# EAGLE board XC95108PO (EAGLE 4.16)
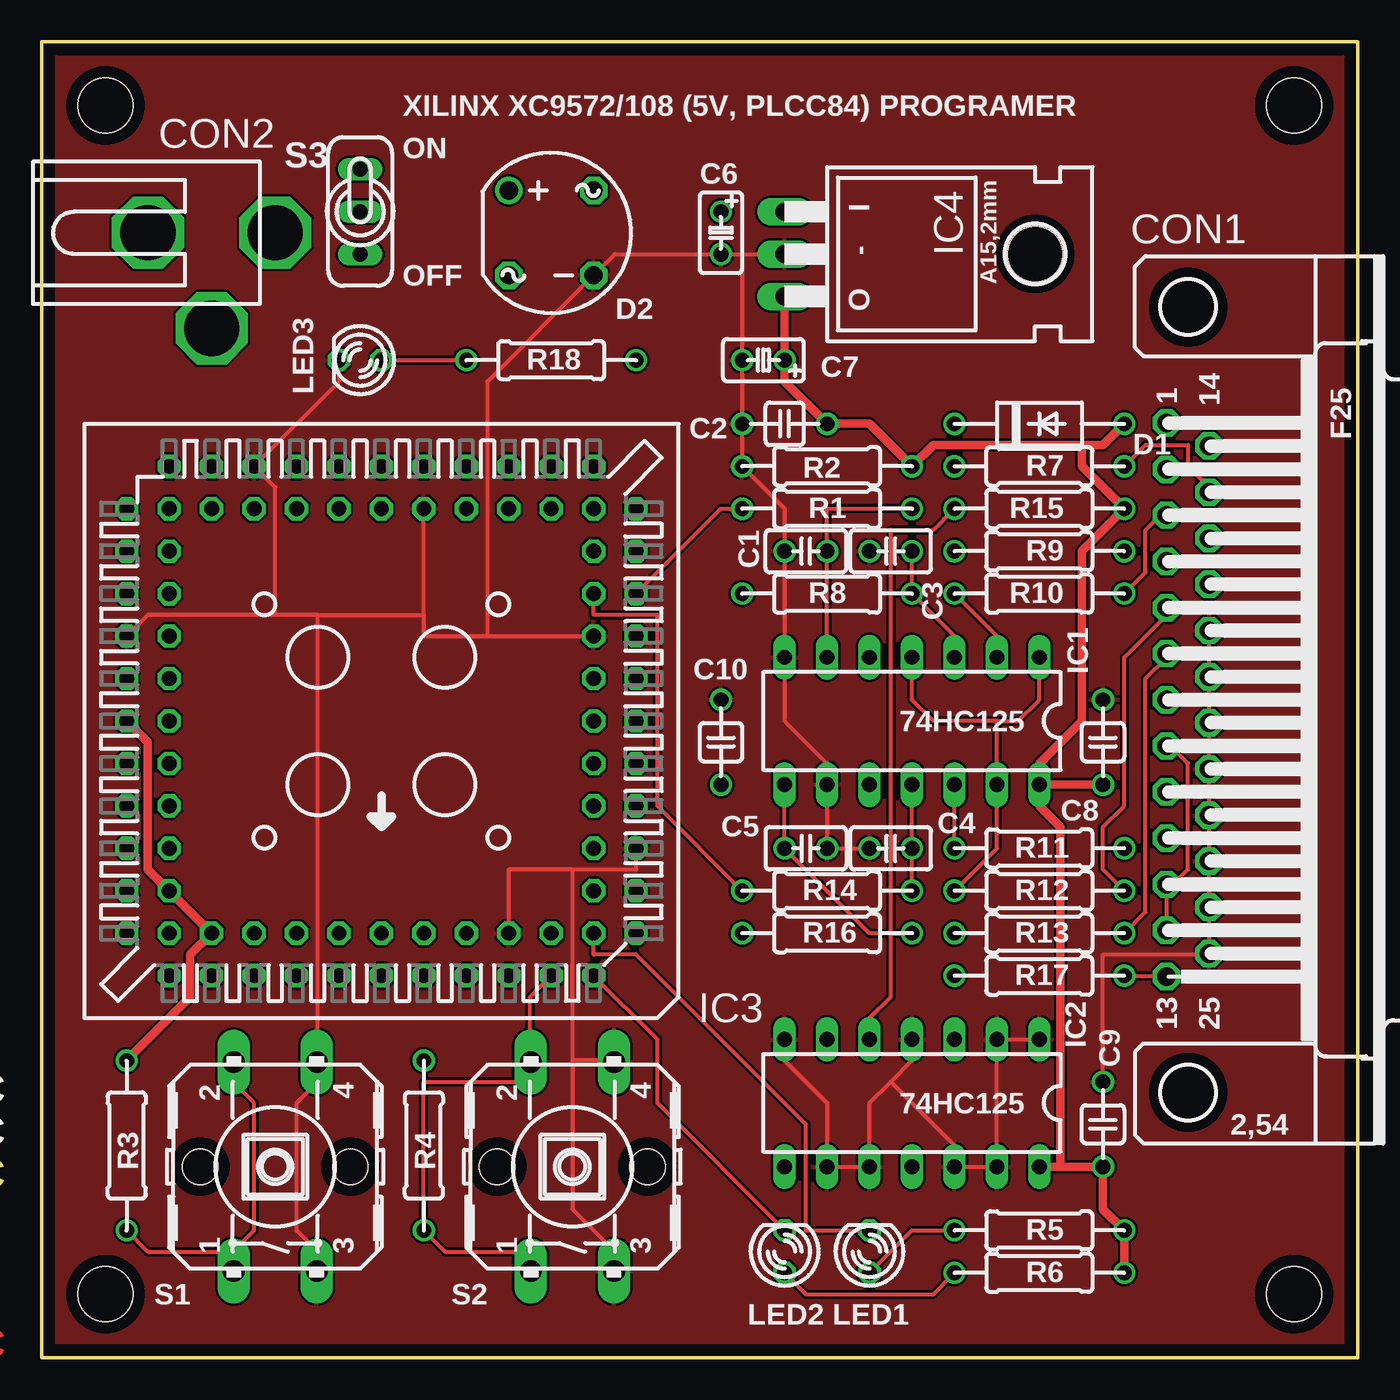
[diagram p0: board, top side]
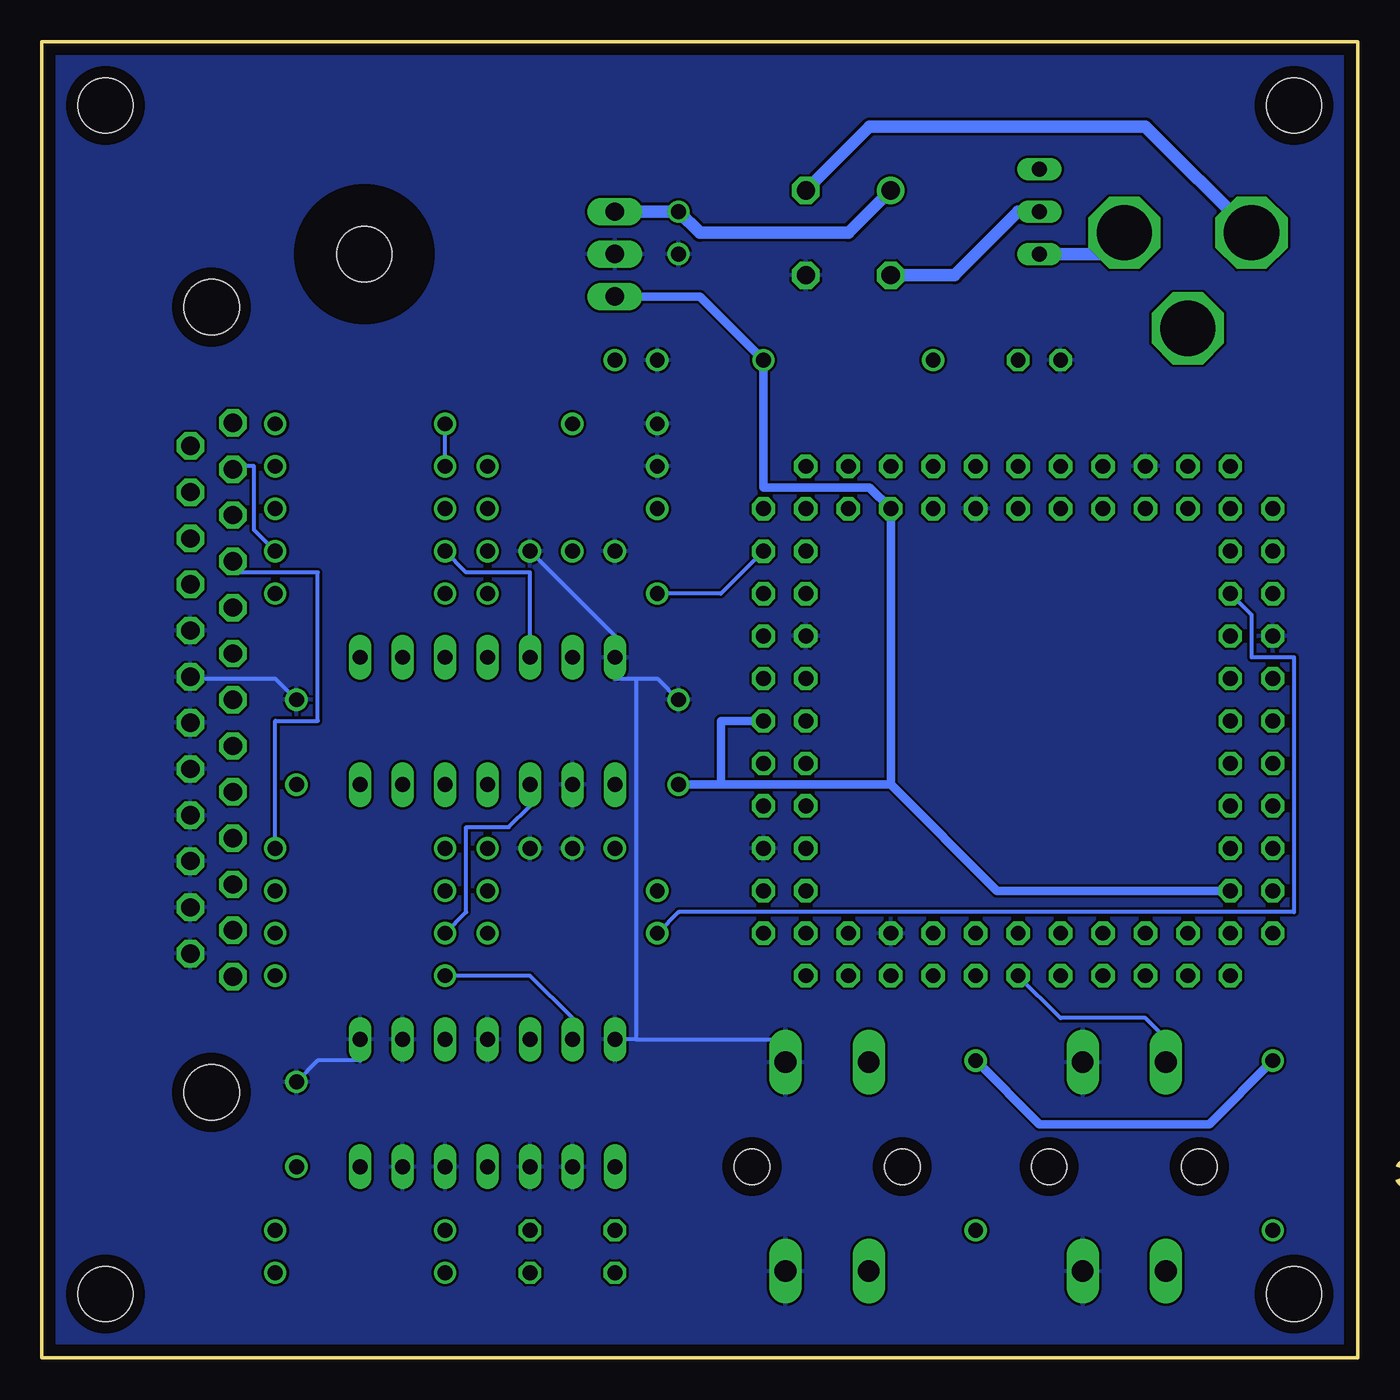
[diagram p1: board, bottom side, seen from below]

Size 78.74 x 78.74 mm. Coordinates in mm from the lower left corner, seen from the top.
Outline: 0,0 0,78.74 78.74,78.74 78.74,0 0,0
Copper layers (1*16): Top 0.035mm / dielectric 1.5mm / Bottom 0.035mm
Design rules "p-ban_min": minimum track width 0.15mm, minimum drill 0.3mm, track to track 0.15mm, track to pad 0.15mm, pad to pad 0.15mm, via to via 0.15mm, smd to smd 0.15mm, copper to edge 0.7mm, drill to drill 0.45mm, minimum pad ring 0.15mm, minimum via ring 0.15mm, stop-mask expansion 4mil, vias tented up to drill 0mil, thermal gap 0.15mm
Net classes: 1 AC: width 0.762 mm; 2 Vcc: width 0.508 mm
Holes 3.3 mm at 74.93,74.93 74.93,3.81 3.81,3.81 3.81,74.93

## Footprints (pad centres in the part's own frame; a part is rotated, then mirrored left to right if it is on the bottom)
C025-025X050 = drill 0.889 round: 1 -1.27,0; 2 1.27,0
PASSCON = drill 0.889 round: 1 -1.27,0; 2 3.81,0
C4518 = drill 0.889 round: + -1.27,0; - 1.27,0
F25H = drill 1.092 octagon: 1 -16.561,-10.16; 2 -13.792,-10.16; 3 -11.049,-10.16; 4 -8.28,-10.16; 5 -5.512,-10.16; 6 -2.769,-10.16; 7 0,-10.16; 8 2.769,-10.16; 9 5.512,-10.16; 10 8.28,-10.16; 11 11.049,-10.16; 12 13.792,-10.16; 13 16.561,-10.16; 14 -15.189,-7.62; 15 -12.421,-7.62; 16 -9.652,-7.62; 17 -6.909,-7.62; 18 -4.14,-7.62; 19 -1.372,-7.62; 20 1.372,-7.62; 21 4.14,-7.62; 22 6.909,-7.62; 23 9.652,-7.62; 24 12.421,-7.62; 25 15.189,-7.62 | hole 3.302: -23.495,-8.89; 23.495,-8.89
SCD-014-A = drill 3.302 octagon: 1 0,12.065; 2 0,4.445; 3 5.715,8.255
DO41-10 = drill 0.889 round: A 5.08,0; C -5.08,0
RB1A = drill 1.092 round: + -2.54,2.54 | drill 1.092 octagon: - 2.54,-2.54; AC1 2.54,2.54; AC2 -2.54,-2.54
DIL14 = drill 0.889 long: 1 -7.62,-3.81; 2 -5.08,-3.81; 3 -2.54,-3.81; 4 0,-3.81; 5 2.54,-3.81; 6 5.08,-3.81; 7 7.62,-3.81; 8 7.62,3.81; 9 5.08,3.81; 10 2.54,3.81; 11 0,3.81; 12 -2.54,3.81; 13 -5.08,3.81; 14 -7.62,3.81
PLCC-S84 = drill 0.889 pad 1.397 octagon: 1 0,15.24; 2 0,12.7; 3 -2.54,15.24; 4 -2.54,12.7; 5 -5.08,15.24; 6 -5.08,12.7; 7 -7.62,15.24; 8 -7.62,12.7; 9 -10.16,15.24; 10 -10.16,12.7; 11 -12.7,15.24; 12 -15.24,12.7; 13 -12.7,12.7; 14 -15.24,10.16; 15 -12.7,10.16; 16 -15.24,7.62; 17 -12.7,7.62; 18 -15.24,5.08; 19 -12.7,5.08; 20 -15.24,2.54; 21 -12.7,2.54; 22 -15.24,0; 23 -12.7,0; 24 -15.24,-2.54; 25 -12.7,-2.54; 26 -15.24,-5.08; 27 -12.7,-5.08; 28 -15.24,-7.62; 29 -12.7,-7.62; 30 -15.24,-10.16; 31 -12.7,-10.16; 32 -15.24,-12.7; 33 -12.7,-15.24; 34 -12.7,-12.7; 35 -10.16,-15.24; 36 -10.16,-12.7; 37 -7.62,-15.24; 38 -7.62,-12.7; 39 -5.08,-15.24; 40 -5.08,-12.7; 41 -2.54,-15.24; 42 -2.54,-12.7; 43 0,-15.24; 44 0,-12.7; 45 2.54,-15.24; 46 2.54,-12.7; 47 5.08,-15.24; 48 5.08,-12.7; 49 7.62,-15.24; 50 7.62,-12.7; 51 10.16,-15.24; 52 10.16,-12.7; 53 12.7,-15.24; 54 15.24,-12.7; 55 12.7,-12.7; 56 15.24,-10.16; 57 12.7,-10.16; 58 15.24,-7.62; 59 12.7,-7.62; 60 15.24,-5.08; 61 12.7,-5.08; 62 15.24,-2.54; 63 12.7,-2.54; 64 15.24,0; 65 12.7,0; 66 15.24,2.54; 67 12.7,2.54; 68 15.24,5.08; 69 12.7,5.08; 70 15.24,7.62; 71 12.7,7.62; 72 15.24,10.16; 73 12.7,10.16; 74 15.24,12.7; 75 12.7,15.24; 76 12.7,12.7; 77 10.16,15.24; 78 10.16,12.7; 79 7.62,15.24; 80 7.62,12.7; 81 5.08,15.24; 82 5.08,12.7; 83 2.54,15.24; 84 2.54,12.7
78XXL = drill 1.092 long: GND 0,-3.81; IN -2.54,-3.81; OUT 2.54,-3.81 | hole 3.302: 0,11.176
LED3MM = drill 0.889 octagon: A -1.27,0; K 1.27,0
0207/10 = drill 0.889 round: 1 -5.08,0; 2 5.08,0
B3F-40XX = drill 1.295 long: 1 -6.248,2.489; 2 6.248,2.489; 3 -6.248,-2.489; 4 6.248,-2.489 | hole 2.108: 0,-4.496; 0,4.496
SW-TOGGLE = drill 0.889 long: 1 0,-2.54; 2 0,0; 3 0,2.54

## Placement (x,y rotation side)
C1  100p  [C025-025X050]  45.72,48.26 180 top
C2  0.01u  [PASSCON]  45.72,55.88 180 top
C3  100p  [C025-025X050]  50.8,48.26 180 top
C4  100p  [C025-025X050]  50.8,30.48 180 top
C5  100p  [C025-025X050]  45.72,30.48 0 top
C6  10u/35V  [C4518]  40.64,67.31 270 top
C7  10u/16V  [C4518]  43.18,59.69 180 top
C8  0.1u  [PASSCON]  63.5,35.56 90 top
C9  0.1u  [PASSCON]  63.5,12.7 90 top
C10  0.1u  [PASSCON]  40.64,35.56 90 top
CON1  [F25H]  77.47,39.37 270 top
CON2  DCJ25  [SCD-014-A]  1.91,67.31 270 top
D1  1S1588  [DO41-10]  59.69,55.88 0 top
D2  W02G  [RB1A]  30.48,67.31 0 top
IC1  74HC125  [DIL14]  52.07,38.1 180 top
IC2  74HC125  [DIL14]  52.07,15.24 180 top
IC3  XC95108PC84  [PLCC-S84]  20.32,38.1 180 top
IC4  7805  [78XXL]  48.26,66.04 270 top
LED1  [LED3MM]  49.53,6.35 90 top
LED2  [LED3MM]  44.45,6.35 90 top
LED3  [LED3MM]  19.05,59.69 180 top
R1  100  [0207/10]  46.99,50.8 180 top
R2  1k  [0207/10]  46.99,53.34 180 top
R3  4.7k  [0207/10]  5.08,12.7 270 top
R4  4.7k  [0207/10]  22.86,12.7 270 top
R5  470  [0207/10]  59.69,7.62 180 top
R6  470  [0207/10]  59.69,5.08 180 top
R7  100  [0207/10]  59.69,53.34 0 top
R8  100  [0207/10]  46.99,45.72 180 top
R9  330  [0207/10]  59.69,48.26 180 top
R10  330  [0207/10]  59.69,45.72 180 top
R11  330  [0207/10]  59.69,30.48 180 top
R12  330  [0207/10]  59.69,27.94 180 top
R13  330  [0207/10]  59.69,25.4 180 top
R14  100  [0207/10]  46.99,27.94 180 top
R15  5.1k  [0207/10]  59.69,50.8 180 top
R16  100  [0207/10]  46.99,25.4 180 top
R17  51  [0207/10]  59.69,22.86 180 top
R18  470  [0207/10]  30.48,59.69 180 top
S1  [B3F-40XX]  13.97,11.43 90 top
S2  [B3F-40XX]  31.75,11.43 90 top
S3  [SW-TOGGLE]  19.05,68.58 180 top

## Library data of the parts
C1-C10 CON1 CON2 D1 D2 IC1 IC2 IC4 LED1-LED3 R1-R18 S3 = xc95108p
IC3 = XILINX
S1 S2 = olimex-r0land

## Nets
GND: C1.2 C2.2 C3.2 C4.2 C5.2 C6.- C7.- C8.2 C9.2 C10.2 CON1.18 CON1.19 CON1.20 CON1.21 CON1.22 CON1.23 CON1.24 CON1.25 D2.- IC1.7 IC1.9 IC2.1 IC2.2 IC2.4 IC2.7 IC2.9 IC2.10 IC2.12 IC2.13 IC3.8 IC3.16 IC3.27 IC3.42 IC3.49 IC3.60 IC4.GND LED3.K R2.2 S1.3 S1.4 S2.3 S2.4
N$1: CON1.4 R11.1
N$2: IC1.5 R9.2
N$3: CON1.2 R9.1
N$4: CON1.3 R10.1
N$5: IC1.2 R10.2
N$6: CON1.15 R7.2
N$7: CON1.8 CON1.11 CON1.12
N$8: CON1.5 R12.1
N$9: CON1.6 R13.1
N$10: IC1.12 R11.2
N$11: IC1.10 R13.2
N$12: IC3.11 LED2.K
N$13: C3.1 IC1.3 R8.1
N$14: CON1.13 R17.1
N$15: D1.C R7.1
N$16: C5.1 IC1.8 IC2.5 R15.2 R16.1
N$17: LED3.A R18.2
N$18: C1.1 IC1.6 R1.1
N$19: IC2.6 R17.2
N$20: C4.1 IC1.11 R14.1
N$21 [AC]: CON2.2 D2.AC1
N$22: IC3.13 LED1.K
N$23 [AC]: C6.+ D2.+ IC4.IN
N$26: IC1.1 IC1.4 IC1.13 R12.2
N$27: IC3.30 R8.2
N$28: IC3.29 R14.2
N$29: IC3.59 R16.2
N$30: IC3.28 R1.2
N$31: IC3.9 R4.2 S2.1 S2.2
N$32: LED1.A R5.2
N$33: LED2.A R6.2
N$34 [AC]: D2.AC2 S3.2
N$35: IC3.1 R3.2 S1.1 S1.2
N$37 [AC]: CON2.1 S3.3
VCC [Vcc]: C2.1 C7.+ C8.1 C9.1 C10.1 D1.A IC1.14 IC2.14 IC3.22 IC3.38 IC3.64 IC3.73 IC3.78 IC4.OUT R2.1 R3.1 R4.1 R5.1 R6.1 R15.1 R18.1

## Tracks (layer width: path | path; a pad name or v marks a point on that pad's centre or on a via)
GND
  Top 0.254: CON1.18 CON1.19 CON1.20 CON1.21 CON1.22 CON1.23 CON1.24 CON1.25 69.85,24.13 63.5,24.13 C9.2 | IC2.7 44.45,17.78 46.99,15.24 IC2.9 IC2.10 49.53,15.24 50.8,16.51 | 50.8,16.51 52.07,17.78 IC2.4 | IC2.1 IC2.2 IC2.13 IC2.12 54.61,12.7 50.8,16.51 | 31.75,29.21 27.94,29.21 IC3.8 | 31.75,29.21 35.56,29.21 IC3.16 | 31.75,17.78 31.75,29.21 | 31.75,17.78 31.75,8.89 34.29,6.35 S2.3 | 31.75,17.78 34.29,17.78 S2.4 | 41.91,66.04 C6.- 34.29,66.04 D2.- 26.67,58.42 26.67,43.18 | 41.91,66.04 IC4.GND | C4.2 C5.2 IC1.9 46.99,35.56 44.45,38.1 IC1.7 C1.2 44.45,50.8 R2.2 C2.2 C7.- 41.91,66.04 | S1.3 16.51,6.35 15.24,7.62 15.24,15.24 16.51,16.51 S1.4 16.51,19.05 16.51,44.45 | LED3.K 17.78,58.42 IC3.49 13.97,52.07 13.97,44.45 | IC3.60 6.35,44.45 13.97,44.45 | 16.51,44.45 22.86,44.45 | 16.51,44.45 13.97,44.45 | 22.86,44.45 IC3.42 | 26.67,43.18 22.86,43.18 22.86,44.45 | 26.67,43.18 IC3.27
  Bottom 0.254: C8.2 64.77,40.64 69.85,40.64 CON1.19 | C9.2 62.23,17.78 59.69,17.78 IC2.1 | 43.18,19.05 34.29,19.05 S2.4 | 43.18,19.05 IC2.7 | C10.2 41.91,40.64 43.18,40.64 | 43.18,40.64 44.45,40.64 IC1.7 44.45,43.18 C3.2 | 43.18,40.64 43.18,19.05
  pour Bottom: 0,78.74 78.74,78.74 78.74,0 0,0
  pour Top: 0,78.74 78.74,78.74 78.74,0 0,0
N$1
  Bottom 0.254: R11.1 64.77,38.1 62.23,38.1 62.23,46.99 67.31,46.99 CON1.4
N$2
  Bottom 0.254: R9.2 53.34,46.99 49.53,46.99 IC1.5
N$3
  Bottom 0.254: R9.1 66.04,49.53 66.04,53.34 67.31,53.34 CON1.2
N$4
  Top 0.254: R10.1 66.04,46.99 66.04,49.53 67.31,50.8 CON1.3
N$5
  Top 0.254: R10.2 57.15,43.18 IC1.2
N$6
  Top 0.254: R7.2 66.04,54.61 68.58,54.61 68.58,53.34 69.85,52.07 CON1.15
N$7
  Top 0.254: 67.31,27.94 CON1.12 67.31,25.4 | 67.31,27.94 68.58,29.21 68.58,35.56 67.31,36.83 CON1.8 | 67.31,27.94 CON1.11
N$8
  Top 0.254: R12.1 63.5,29.21 63.5,31.75 64.77,33.02 64.77,41.91 67.31,44.45 CON1.5
N$9
  Top 0.254: R13.1 66.04,26.67 66.04,40.64 67.31,41.91 CON1.6
N$10
  Top 0.254: R11.2 IC1.12
N$11
  Bottom 0.254: R13.2 53.34,26.67 53.34,31.75 50.8,31.75 49.53,33.02 IC1.10
N$12
  Top 0.254: LED2.K 36.83,15.24 36.83,19.05 IC3.11
N$13
  Top 0.254: C3.1 R8.1 54.61,43.18 IC1.3
N$14
  Top 0.254: R17.1 67.31,22.86 CON1.13
N$15
  Bottom 0.254: R7.1 D1.C
N$16
  Top 0.254: IC1.8 C5.1 49.53,25.4 50.8,25.4 | 50.8,25.4 R16.1 | IC2.5 49.53,20.32 50.8,21.59 50.8,25.4 | R15.2 53.34,49.53 50.8,49.53 50.8,25.4
N$17
  Top 0.254: LED3.A R18.2
N$18
  Top 0.254: IC1.6 C1.1 46.99,50.8 R1.1
N$19
  Bottom 0.254: R17.2 49.53,22.86 46.99,20.32 IC2.6
N$20
  Top 0.254: R14.1 C4.1 IC1.11
N$21
  Bottom 0.762: D2.AC1 29.21,73.66 12.7,73.66 CON2.2
N$22
  Top 0.254: LED1.K 45.72,7.62 45.72,13.97 35.56,24.13 33.02,24.13 IC3.13
N$23
  Bottom 0.762: IC4.IN C6.+ 39.37,67.31 30.48,67.31 D2.+
N$26
  Top 0.254: R12.2 57.15,30.48 IC1.13 57.15,38.1 | 57.15,38.1 53.34,38.1 52.07,39.37 IC1.4 | 57.15,38.1 58.42,38.1 59.69,39.37 IC1.1
N$27
  Bottom 0.254: IC3.30 38.1,45.72 R8.2
N$28
  Top 0.254: R14.2 36.83,33.02 36.83,44.45 33.02,44.45 IC3.29
N$29
  Bottom 0.254: IC3.59 6.35,44.45 6.35,41.91 3.81,41.91 3.81,26.67 40.64,26.67 R16.2
N$30
  Top 0.254: IC3.28 40.64,50.8 R1.2
N$31
  Top 0.254: IC3.9 29.21,21.59 29.21,19.05 S2.2 29.21,16.51 22.86,16.51 R4.2 24.13,6.35 29.21,6.35 S2.1
N$32
  Top 0.254: LED1.A 52.07,7.62 R5.2
N$33
  Top 0.254: LED2.A 45.72,3.81 53.34,3.81 R6.2
N$34
  Bottom 0.762: D2.AC2 24.13,64.77 20.32,68.58 S3.2
N$35
  Top 0.254: R3.2 6.35,6.35 11.43,6.35 | 11.43,6.35 12.7,7.62 12.7,15.24 11.43,16.51 S1.2 | 11.43,6.35 S1.1
  Bottom 0.254: S1.1 11.43,6.35 | IC3.1 17.78,20.32 12.7,20.32 11.43,19.05 S1.2
N$37
  Bottom 0.762: S3.3 15.24,66.04 CON2.1
VCC
  Top 0.508: R3.1 8.89,21.59 8.89,24.13 IC3.78 | IC3.78 IC3.73 | IC3.64 6.35,36.83 6.35,29.21 IC3.73 | IC3.78 IC3.73 | IC1.14 C8.1 | R6.1 R5.1 63.5,8.89 C9.1 60.96,11.43 | 60.96,11.43 IC2.14 | 60.96,11.43 60.96,31.75 59.69,33.02 IC1.14 | IC4.OUT C7.+ 44.45,58.42 C2.1 49.53,55.88 R2.1 53.34,54.61 62.23,54.61 | 62.23,54.61 62.23,53.34 R15.1 62.23,48.26 62.23,38.1 59.69,35.56 IC1.14 | 62.23,54.61 63.5,54.61 D1.A
  Bottom 0.508: 27.94,34.29 IC3.38 29.21,52.07 35.56,52.07 R18.1 39.37,63.5 IC4.OUT | 39.37,34.29 C10.1 | 27.94,34.29 39.37,34.29 | 39.37,34.29 38.1,34.29 38.1,38.1 IC3.22 | R4.1 19.05,13.97 8.89,13.97 R3.1 | 27.94,34.29 21.59,27.94 IC3.73

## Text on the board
Top: ABC
Bottom: ABC
Pads: ABC
Vias: ABC
Dimension: ABC
tPlace: XILINX XC9572/108 (5V, PLCC84) PROGRAMER | ON | OFF | ABC
tNames: ABC
tStop: ABC
bStop: ABC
